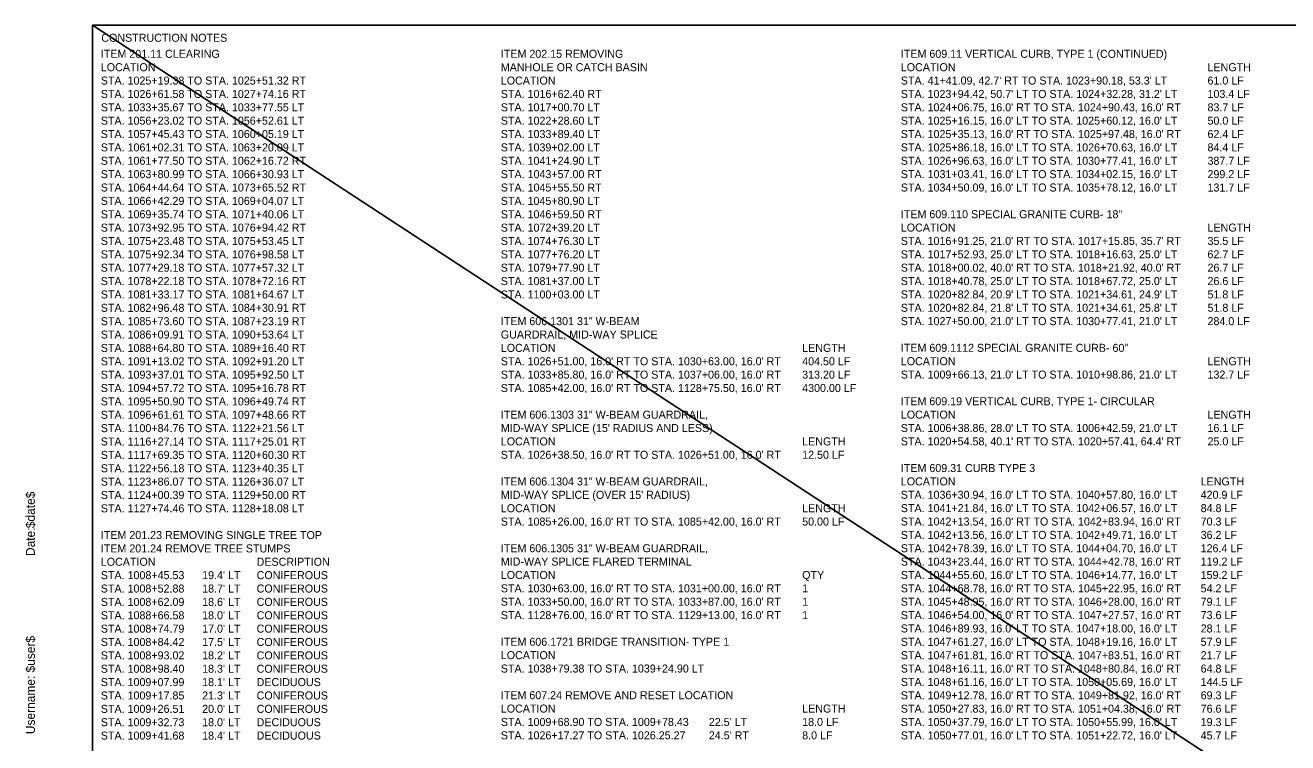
# Model space of a CAD drawing. Extents: x -831 to 3331, y -1004 to 250.
# Drawn here: x 117.9 to 591.3, y -19.2 to 249.7 of the extents above; entities that cross this region are included whole.
import ezdxf

# ---------------------------------------------------------------- set-up
doc = ezdxf.new("R2010")
doc.units = 0
doc.layers.add('BORDER', color=7, linetype='Continuous')
doc.layers.add('Default', color=7, linetype='Continuous')

msp = doc.modelspace()

# ---------------------------------------------------------------- linework, layer by layer
at = {"layer": 'BORDER'}
msp.add_lwpolyline([(143.03, 249.69), (943.03, 249.69), (943.03, -275.31), (143.03, -275.31)], close=True, dxfattribs=at)
at = {"layer": 'Default'}
for p, q in [((143.03, 249.69), (958.96, -283.29)), ((509.71, 249.69), (513.05, 249.69))]:
    msp.add_line(p, q, dxfattribs=at)

# ---------------------------------------------------------------- texts
at = {"layer": 'BORDER'}
for s, p in [('$date$', (121.46, 61.22)), ('Date:', (121.46, 50.78)), ('$user$', (121.46, 7.15)), ('Username:', (121.46, -15.97))]:
    msp.add_text(s, height=3.348, rotation=90, dxfattribs=at).set_placement(p)
at = {"layer": 'Default'}
for s, p in [('CONSTRUCTION NOTES', (146.37, 243.51)), ('ITEM 201.11 CLEARING', (146.19, 237.49)), ('ITEM 202.15 REMOVING ', (296.19, 237.49)), ('ITEM 609.11 VERTICAL CURB, TYPE 1 (CONTINUED)', (446.19, 237.49)), ('LOCATION', (146.19, 232.48)), ('MANHOLE OR CATCH BASIN', (296.19, 232.48)), ('LOCATION', (446.19, 232.48)), ('LENGTH', (561.19, 232.48)), ('STA. 1025+19.38 TO STA. 1025+51.32 RT', (146.19, 227.47)), ('LOCATION', (296.19, 227.47)), ("STA. 41+41.09, 42.7' RT TO STA. 1023+90.18, 53.3' LT", (446.19, 227.47)), ('61.0 LF', (561.19, 227.47)), ('STA. 1026+61.58 TO STA. 1027+74.16 RT', (146.19, 222.46)), ('STA. 1016+62.40 RT', (296.19, 222.46)), ("STA. 1023+94.42, 50.7' LT TO STA. 1024+32.28, 31.2' LT", (446.19, 222.46)), ('103.4 LF', (561.19, 222.46)), ('STA. 1033+35.67 TO STA. 1033+77.55 LT', (146.19, 217.45)), ('STA. 1017+00.70 LT', (296.19, 217.45)), ("STA. 1024+06.75, 16.0' RT TO STA. 1024+90.43, 16.0' RT", (446.19, 217.45)), ('83.7 LF', (561.19, 217.45)), ('STA. 1056+23.02 TO STA. 1056+52.61 LT', (146.19, 212.44)), ('STA. 1022+28.60 LT', (296.19, 212.44)), ("STA. 1025+16.15, 16.0' LT TO STA. 1025+60.12, 16.0' LT", (446.19, 212.44)), ('50.0 LF', (561.19, 212.44)), ('STA. 1057+45.43 TO STA. 1060+05.19 LT', (146.19, 207.43)), ('STA. 1033+89.40 LT', (296.19, 207.43)), ("STA. 1025+35.13, 16.0' RT TO STA. 1025+97.48, 16.0' RT", (446.19, 207.43)), ('62.4 LF', (561.19, 207.43)), ('STA. 1061+02.31 TO STA. 1063+20.09 LT', (146.19, 202.42)), ('STA. 1039+02.00 LT', (296.19, 202.42)), ("STA. 1025+86.18, 16.0' LT TO STA. 1026+70.63, 16.0' LT", (446.19, 202.42)), ('84.4 LF', (561.19, 202.42)), ('STA. 1061+77.50 TO STA. 1062+16.72 RT', (146.19, 197.41)), ('STA. 1041+24.90 LT', (296.19, 197.41)), ("STA. 1026+96.63, 16.0' LT TO STA. 1030+77.41, 16.0' LT", (446.19, 197.41)), ('387.7 LF', (561.19, 197.41)), ('STA. 1063+80.99 TO STA. 1066+30.93 LT', (146.19, 192.4)), ('STA. 1043+57.00 RT', (296.19, 192.4)), ("STA. 1031+03.41, 16.0' LT TO STA. 1034+02.15, 16.0' LT", (446.19, 192.4)), ('299.2 LF', (561.19, 192.4)), ('STA. 1064+44.64 TO STA. 1073+65.52 RT', (146.19, 187.39)), ('STA. 1045+55.50 RT', (296.19, 187.39)), ("STA. 1034+50.09, 16.0' LT TO STA. 1035+78.12, 16.0' LT", (446.19, 187.39)), ('131.7 LF', (561.19, 187.39)), ('STA. 1066+42.29 TO STA. 1069+04.07 LT', (146.19, 182.38)), ('STA. 1045+80.90 LT', (296.19, 182.38)), ('STA. 1069+35.74 TO STA. 1071+40.06 LT', (146.19, 177.37)), ('STA. 1046+59.50 RT', (296.19, 177.37)), ('ITEM 609.110 SPECIAL GRANITE CURB- 18"', (446.19, 177.39)), ('STA. 1073+92.95 TO STA. 1076+94.42 RT', (146.19, 172.36)), ('STA. 1072+39.20 LT', (296.19, 172.36)), ('LOCATION', (446.19, 172.38)), ('LENGTH', (561.19, 172.38)), ('STA. 1075+23.48 TO STA. 1075+53.45 LT', (146.19, 167.35)), ('STA. 1074+76.30 LT', (296.19, 167.35)), ("STA. 1016+91.25, 21.0' RT TO STA. 1017+15.85, 35.7' RT", (446.19, 167.37)), ('35.5 LF', (561.19, 167.37)), ('STA. 1075+92.34 TO STA. 1076+98.58 LT', (146.19, 162.34)), ('STA. 1077+76.20 LT', (296.19, 162.34)), ("STA. 1017+52.93, 25.0' LT TO STA. 1018+16.63, 25.0' LT", (446.19, 162.36)), ('62.7 LF', (561.19, 162.36)), ('STA. 1077+29.18 TO STA. 1077+57.32 LT', (146.19, 157.33)), ('STA. 1079+77.90 LT', (296.19, 157.33)), ("STA. 1018+00.02, 40.0' RT TO STA. 1018+21.92, 40.0' RT", (446.19, 157.35)), ('26.7 LF', (561.19, 157.35)), ('STA. 1078+22.18 TO STA. 1078+72.16 RT', (146.19, 152.32)), ('STA. 1081+37.00 LT', (296.19, 152.32)), ("STA. 1018+40.78, 25.0' LT TO STA. 1018+67.72, 25.0' LT ", (446.19, 152.34)), ('26.6 LF', (561.19, 152.34)), ('STA. 1081+33.17 TO STA. 1081+64.67 LT', (146.19, 147.31)), ('STA. 1100+03.00 LT', (296.19, 147.31)), ("STA. 1020+82.84, 20.9' LT TO STA. 1021+34.61, 24.9' LT", (446.19, 147.33)), ('51.8 LF', (561.19, 147.33)), ('STA. 1082+96.48 TO STA. 1084+30.91 RT', (146.19, 142.3)), ("STA. 1020+82.84, 21.8' LT TO STA. 1021+34.61, 25.8' LT", (446.19, 142.32)), ('51.8 LF', (561.19, 142.32)), ('STA. 1085+73.60 TO STA. 1087+23.19 RT', (146.19, 137.29)), ('ITEM 606.1301 31" W-BEAM ', (296.19, 137.31)), ("STA. 1027+50.00, 21.0' LT TO STA. 1030+77.41, 21.0' LT", (446.19, 137.31)), ('284.0 LF', (561.19, 137.31)), ('STA. 1086+09.91 TO STA. 1090+53.64 LT', (146.19, 132.28)), ('GUARDRAIL, MID-WAY SPLICE', (296.19, 132.3)), ('STA. 1088+64.80 TO STA. 1089+16.40 RT', (146.19, 127.27)), ('LOCATION', (296.19, 127.29)), ('LENGTH', (409.19, 127.29)), ('ITEM 609.1112 SPECIAL GRANITE CURB- 60"', (446.19, 127.31)), ('STA. 1091+13.02 TO STA. 1092+91.20 LT', (146.19, 122.26)), ("STA. 1026+51.00, 16.0' RT TO STA. 1030+63.00, 16.0' RT", (296.19, 122.28)), ('404.50 LF', (409.19, 122.28)), ('LOCATION', (446.19, 122.3)), ('LENGTH', (561.19, 122.3)), ('STA. 1093+37.01 TO STA. 1095+92.50 LT', (146.19, 117.25)), ("STA. 1033+85.80, 16.0' RT TO STA. 1037+06.00, 16.0' RT", (296.19, 117.27)), ('313.20 LF', (409.19, 117.27)), ("STA. 1009+66.13, 21.0' LT TO STA. 1010+98.86, 21.0' LT", (446.19, 117.29)), ('132.7 LF', (561.19, 117.29)), ('STA. 1094+57.72 TO STA. 1095+16.78 RT', (146.19, 112.24)), ("STA. 1085+42.00, 16.0' RT TO STA. 1128+75.50, 16.0' RT", (296.19, 112.26)), ('4300.00 LF', (409.19, 112.26)), ('STA. 1095+50.90 TO STA. 1096+49.74 RT', (146.19, 107.23)), ('ITEM 609.19 VERTICAL CURB, TYPE 1- CIRCULAR', (446.19, 107.29)), ('STA. 1096+61.61 TO STA. 1097+48.66 RT', (146.19, 102.22)), ('ITEM 606.1303 31" W-BEAM GUARDRAIL, ', (296.19, 102.26)), ('LOCATION', (446.19, 102.28)), ('LENGTH', (561.19, 102.28)), ('STA. 1100+84.76 TO STA. 1122+21.56 LT', (146.19, 97.21)), ("MID-WAY SPLICE (15' RADIUS AND LESS)", (296.19, 97.25)), ("STA. 1006+38.86, 28.0' LT TO STA. 1006+42.59, 21.0' LT", (446.19, 97.27)), ('16.1 LF', (561.19, 97.27)), ('STA. 1116+27.14 TO STA. 1117+25.01 RT', (146.19, 92.2)), ('LOCATION', (296.19, 92.24)), ('LENGTH', (409.19, 92.24)), ("STA. 1020+54.58, 40.1' RT TO STA. 1020+57.41, 64.4' RT", (446.19, 92.26)), ('25.0 LF', (561.19, 92.26)), ('STA. 1117+69.35 TO STA. 1120+60.30 RT', (146.19, 87.19)), ("STA. 1026+38.50, 16.0' RT TO STA. 1026+51.00, 16.0' RT", (296.19, 87.23)), ('12.50 LF', (409.19, 87.23)), ('STA. 1122+56.18 TO STA. 1123+40.35 LT', (146.19, 82.18)), ('ITEM 609.31 CURB TYPE 3', (446.19, 82.26)), ('STA. 1123+86.07 TO STA. 1126+36.07 LT', (146.19, 77.17)), ('ITEM 606.1304 31" W-BEAM GUARDRAIL, ', (296.19, 77.23)), ('LOCATION', (446.19, 77.25)), ('LENGTH', (558.62, 77.25)), ('STA. 1124+00.39 TO STA. 1129+50.00 RT', (146.19, 72.16)), ("MID-WAY SPLICE (OVER 15' RADIUS)", (296.19, 72.22)), ("STA. 1036+30.94, 16.0' LT TO STA. 1040+57.80, 16.0' LT", (446.19, 72.24)), ('420.9 LF', (558.62, 72.24)), ('STA. 1127+74.46 TO STA. 1128+18.08 LT', (146.19, 67.15)), ('LOCATION', (296.19, 67.21)), ('LENGTH', (409.19, 67.21)), ("STA. 1041+21.84, 16.0' LT TO STA. 1042+06.57, 16.0' LT", (446.19, 67.23)), ('84.8 LF', (558.62, 67.23)), ("STA. 1085+26.00, 16.0' RT TO STA. 1085+42.00, 16.0' RT", (296.19, 62.2)), ('50.00 LF', (409.19, 62.2)), ("STA. 1042+13.54, 16.0' RT TO STA. 1042+83.94, 16.0' RT", (446.19, 62.22)), ('70.3 LF', (558.62, 62.22)), ('ITEM 201.23 REMOVING SINGLE TREE TOP', (146.19, 57.15)), ("STA. 1042+13.56, 16.0' LT TO STA. 1042+49.71, 16.0' LT", (446.19, 57.21)), ('36.2 LF', (558.62, 57.21)), ('ITEM 201.24 REMOVE TREE STUMPS', (146.19, 52.14)), ('ITEM 606.1305 31" W-BEAM GUARDRAIL, ', (296.19, 52.2)), ("STA. 1042+78.39, 16.0' LT TO STA. 1044+04.70, 16.0' LT", (446.19, 52.2)), ('126.4 LF', (558.62, 52.2)), ('LOCATION', (146.19, 47.13)), ('DESCRIPTION', (204.62, 47.13)), ('MID-WAY SPLICE FLARED TERMINAL', (296.19, 47.19)), ("STA. 1043+23.44, 16.0' RT TO STA. 1044+42.78, 16.0' RT", (446.19, 47.19)), ('119.2 LF', (558.62, 47.19)), ('STA. 1008+45.53 ', (146.19, 42.12)), ("19.4' LT", (184.19, 42.12)), ('CONIFEROUS', (204.62, 42.12)), ('LOCATION', (296.19, 42.18)), ('QTY', (409.19, 42.18)), ("STA. 1044+55.60, 16.0' LT TO STA. 1046+14.77, 16.0' LT", (446.19, 42.18)), ('159.2 LF', (558.62, 42.18)), ('STA. 1008+52.88', (146.19, 37.11)), ("18.7' LT", (184.19, 37.11)), ('CONIFEROUS', (204.62, 37.11)), ("STA. 1030+63.00, 16.0' RT TO STA. 1031+00.00, 16.0' RT", (296.19, 37.17)), ('1', (409.19, 37.17)), ("STA. 1044+68.78, 16.0' RT TO STA. 1045+22.95, 16.0' RT", (446.19, 37.17)), ('54.2 LF', (558.62, 37.17)), ('STA. 1008+62.09', (146.19, 32.1)), ("18.6' LT", (184.19, 32.1)), ('CONIFEROUS', (204.62, 32.1)), ("STA. 1033+50.00, 16.0' RT TO STA. 1033+87.00, 16.0' RT", (296.19, 32.16)), ('1', (409.19, 32.16)), ("STA. 1045+48.95, 16.0' RT TO STA. 1046+28.00, 16.0' RT", (446.19, 32.16)), ('79.1 LF', (558.62, 32.16)), ('STA. 1088+66.58', (146.19, 27.09)), ("18.0' LT", (184.19, 27.09)), ('CONIFEROUS', (204.62, 27.09)), ("STA. 1128+76.00, 16.0' RT TO STA. 1129+13.00, 16.0' RT", (296.19, 27.15)), ('1', (409.19, 27.15)), ("STA. 1046+54.00, 16.0' RT TO STA. 1047+27.57, 16.0' RT", (446.19, 27.15)), ('73.6 LF', (558.62, 27.15)), ('STA. 1008+74.79', (146.19, 22.08)), ("17.0' LT", (184.19, 22.08)), ('CONIFEROUS', (204.62, 22.08)), ("STA. 1046+89.93, 16.0' LT TO STA. 1047+18.00, 16.0' LT", (446.19, 22.14)), ('28.1 LF', (558.62, 22.14)), ('STA. 1008+84.42', (146.19, 17.07)), ("17.5' LT", (184.19, 17.07)), ('CONIFEROUS', (204.62, 17.07)), ('ITEM 606.1721 BRIDGE TRANSITION- TYPE 1', (296.19, 17.15)), ("STA. 1047+61.27, 16.0' LT TO STA. 1048+19.16, 16.0' LT", (446.19, 17.13)), ('57.9 LF', (558.62, 17.13)), ('STA. 1008+93.02', (146.19, 12.06)), ("18.2' LT", (184.19, 12.06)), ('CONIFEROUS', (204.62, 12.06)), ('LOCATION', (296.19, 12.14)), ("STA. 1047+61.81, 16.0' RT TO STA. 1047+83.51, 16.0' RT", (446.19, 12.12)), ('21.7 LF', (558.62, 12.12)), ('STA. 1008+98.40', (146.19, 7.05)), ("18.3' LT", (184.19, 7.05)), ('CONIFEROUS', (204.62, 7.05)), ('STA. 1038+79.38 TO STA. 1039+24.90 LT', (296.19, 7.13)), ("STA. 1048+16.11, 16.0' RT TO STA. 1048+80.84, 16.0' RT", (446.19, 7.11)), ('64.8 LF', (558.62, 7.11)), ('STA. 1009+07.99', (146.19, 2.04)), ("18.1' LT", (184.19, 2.04)), ('DECIDUOUS', (204.62, 2.04)), ("STA. 1048+61.16, 16.0' LT TO STA. 1050+05.69, 16.0' LT", (446.19, 2.1)), ('144.5 LF', (558.62, 2.1)), ('STA. 1009+17.85', (146.19, -2.97)), ("21.3' LT", (184.19, -2.97)), ('CONIFEROUS', (204.62, -2.97)), ('ITEM 607.24 REMOVE AND RESET LOCATION', (296.19, -2.87)), ("STA. 1049+12.78, 16.0' RT TO STA. 1049+81.92, 16.0' RT", (446.19, -2.91)), ('69.3 LF', (558.62, -2.91)), ('STA. 1009+26.51', (146.19, -7.98)), ("20.0' LT", (184.19, -7.98)), ('CONIFEROUS', (204.62, -7.98)), ('LOCATION', (296.19, -7.88)), ('LENGTH', (409.19, -7.88)), ("STA. 1050+27.83, 16.0' RT TO STA. 1051+04.38, 16.0' RT", (446.19, -7.92)), ('76.6 LF', (558.62, -7.92)), ('STA. 1009+32.73', (146.19, -12.99)), ("18.0' LT", (184.19, -12.99)), ('DECIDUOUS', (204.62, -12.99)), ('STA. 1009+68.90 TO STA. 1009+78.43', (296.19, -12.89)), ("22.5' LT", (374.19, -12.89)), ('18.0 LF', (409.19, -12.89)), ("STA. 1050+37.79, 16.0' LT TO STA. 1050+55.99, 16.0' LT", (446.19, -12.93)), ('19.3 LF', (558.62, -12.93)), ('STA. 1009+41.68', (146.19, -18)), ("18.4' LT", (184.19, -18)), ('DECIDUOUS', (204.62, -18)), ('STA. 1026+17.27 TO STA. 1026.25.27', (296.19, -17.9)), ("24.5' RT", (374.19, -17.9)), ('8.0 LF', (409.19, -17.9)), ("STA. 1050+77.01, 16.0' LT TO STA. 1051+22.72, 16.0' LT", (446.19, -17.94)), ('45.7 LF', (558.62, -17.94))]:
    msp.add_text(s, height=3, dxfattribs=at).set_placement(p)

doc.saveas('drawing.dxf')
